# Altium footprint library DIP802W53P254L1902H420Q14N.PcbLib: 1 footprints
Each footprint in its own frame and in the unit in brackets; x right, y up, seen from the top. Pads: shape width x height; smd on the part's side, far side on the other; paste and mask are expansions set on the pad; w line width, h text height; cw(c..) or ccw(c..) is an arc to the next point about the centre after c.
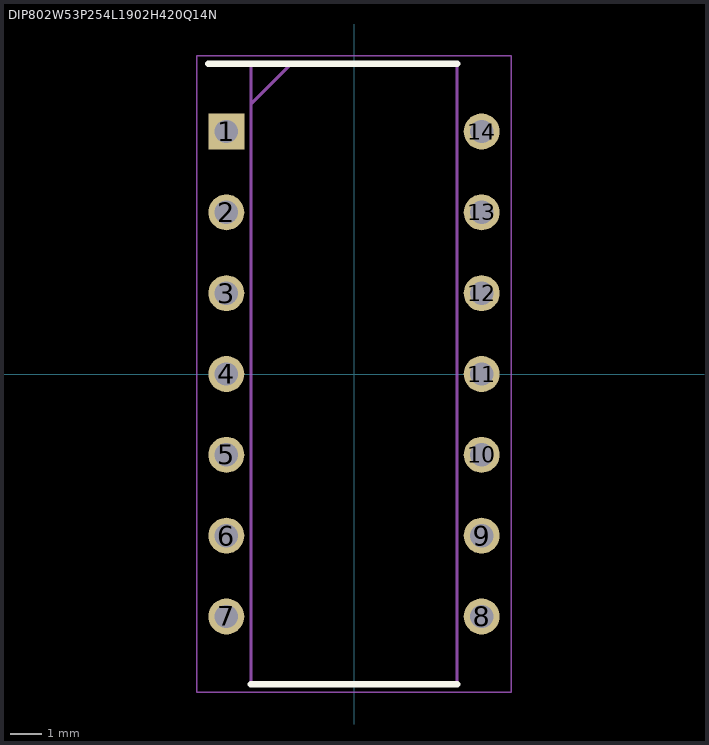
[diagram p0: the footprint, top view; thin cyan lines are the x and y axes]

## DIP802W53P254L1902H420Q14N [mm]
pads (14):
  rect 1.13x1.13 / inner round 1.13 / far side rect 1.13x1.13 hole 0.73: 1(-4.012,7.62)
  round 1.13 hole 0.73: 2(-4.012,5.08) 3(-4.012,2.54) 4(-4.012,0) 5(-4.012,-2.54) 6(-4.012,-5.08) 7(-4.012,-7.62) 8(4.012,-7.62) 9(4.012,-5.08) 10(4.012,-2.54) 11(4.012,0) 12(4.012,2.54) 13(4.012,5.08) 14(4.012,7.62)
Top Overlay:
  lines w0.2: -4.578,9.75 3.24,9.75 ; -3.24,-9.75 3.24,-9.75
Mechanical 15:
  lines w0.1: -3.24,8.48 -1.97,9.75 ; -3.24,-9.75 3.24,-9.75 3.24,9.75 -3.24,9.75 -3.24,-9.75
Mechanical 20:
  lines w0.05: -4.94,-10 4.94,-10 4.94,10 -4.94,10 -4.94,-10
